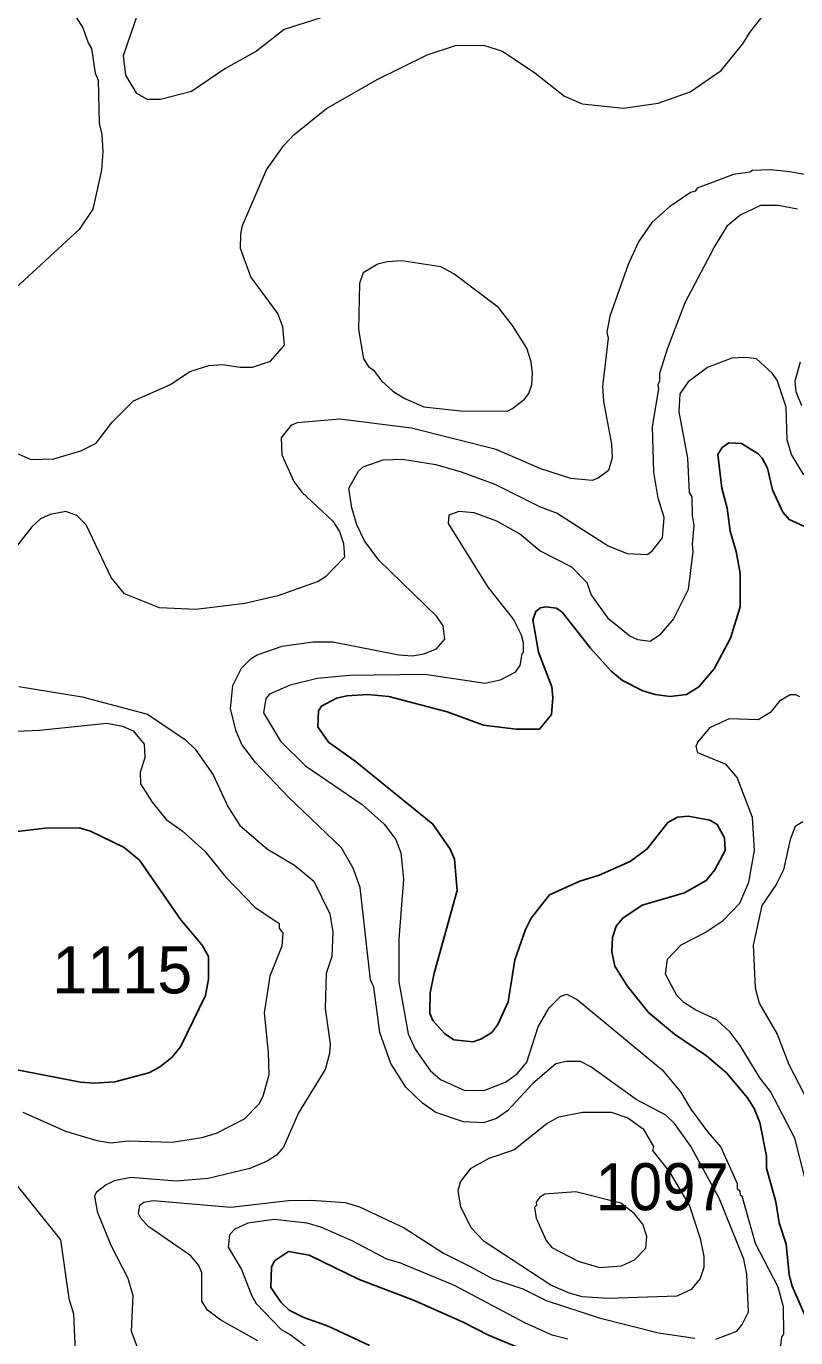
# Model space of a CAD drawing. Extents: x 447.8 to 473.9, y 7733.1 to 7760.8.
# Drawn here: x 470.525 to 471.833, y 7748.242 to 7750.473 of the extents above; entities that cross this region are included whole.
import ezdxf

# ---------------------------------------------------------------- set-up
doc = ezdxf.new("R2010")
doc.units = 0
doc.header["$LTSCALE"] = 0.032
doc.layers.add('1', color=7, linetype='Continuous', lineweight=25)
doc.layers.add('2', color=7, linetype='Continuous', lineweight=13)
doc.layers.add('21', color=7, linetype='Continuous')

msp = doc.modelspace()

# ---------------------------------------------------------------- linework, layer by layer
at = {"layer": '1'}
for points in [[(471.8474, 7749.6229), (471.8221, 7749.634), (471.8112, 7749.6468), (471.7936, 7749.6846), (471.7851, 7749.7213), (471.7765, 7749.7386), (471.7696, 7749.7458), (471.7411, 7749.7634), (471.7193, 7749.7647), (471.7085, 7749.7567), (471.7009, 7749.7449), (471.7075, 7749.6873), (471.7169, 7749.6532), (471.7221, 7749.6141), (471.7323, 7749.5799), (471.7386, 7749.5422), (471.7386, 7749.4858), (471.7225, 7749.4324), (471.6947, 7749.3801), (471.6687, 7749.3492), (471.6473, 7749.3366), (471.6197, 7749.3333), (471.5941, 7749.3366), (471.5731, 7749.3429), (471.539, 7749.3602), (471.5196, 7749.3761), (471.4842, 7749.4153), (471.4362, 7749.4762), (471.4263, 7749.483), (471.4085, 7749.4856), (471.3994, 7749.4838), (471.3911, 7749.4778), (471.3861, 7749.4635), (471.3961, 7749.4086), (471.4188, 7749.3494), (471.4204, 7749.3305), (471.4178, 7749.3027), (471.3973, 7749.2774), (471.3578, 7749.2774), (471.3023, 7749.2845), (471.2405, 7749.3068), (471.1411, 7749.3333), (471.1058, 7749.3365), (471.0702, 7749.3341), (471.0522, 7749.33), (471.0271, 7749.3167), (471.022, 7749.3085), (471.0205, 7749.2815), (471.0386, 7749.2552), (471.0842, 7749.2232), (471.2162, 7749.1159), (471.2457, 7749.0736), (471.2528, 7749.0564), (471.2577, 7749.0028), (471.2185, 7748.8624), (471.2116, 7748.8292), (471.2112, 7748.7947), (471.2163, 7748.7818), (471.2358, 7748.7597), (471.2517, 7748.749), (471.2849, 7748.7459), (471.2988, 7748.7506), (471.3163, 7748.7614), (471.3266, 7748.7754), (471.3442, 7748.8136), (471.3556, 7748.8849), (471.3737, 7748.9367), (471.3836, 7748.9563), (471.4147, 7748.9957), (471.4662, 7749.0191), (471.4991, 7749.0293), (471.5518, 7749.0524), (471.5809, 7749.0739), (471.6161, 7749.1185), (471.6325, 7749.1279), (471.6505, 7749.1297), (471.6873, 7749.1225)], [(471.6873, 7749.1225), (471.6999, 7749.1154), (471.7122, 7749.0926), (471.7131, 7749.0712), (471.6959, 7749.0382), (471.6813, 7749.0199)], [(470.4613, 7749.0978), (470.5568, 7749.1089), (470.6148, 7749.1097), (470.6341, 7749.1041), (470.6915, 7749.0762), (470.7172, 7749.0546), (470.7876, 7748.9534), (470.824, 7748.9101), (470.8344, 7748.8906), (470.8344, 7748.8521), (470.8293, 7748.8245), (470.7872, 7748.7371), (470.7724, 7748.7191), (470.7516, 7748.7024), (470.7332, 7748.6929), (470.6754, 7748.6776), (470.6399, 7748.6753), (470.6172, 7748.6769), (470.4645, 7748.7065)], [(471.6813, 7749.0199), (471.6439, 7748.999), (471.5723, 7748.9783), (471.5393, 7748.956), (471.5279, 7748.9422), (471.5215, 7748.9229), (471.5207, 7748.8986), (471.5255, 7748.8741), (471.5465, 7748.8412), (471.583, 7748.7957), (471.6271, 7748.7589), (471.6816, 7748.722), (471.7156, 7748.6927), (471.7513, 7748.6507), (471.7629, 7748.6325), (471.7724, 7748.6084), (471.7835, 7748.5514), (471.7837, 7748.531), (471.7996, 7748.4738), (471.8052, 7748.4376), (471.8173, 7748.4016), (471.822, 7748.3494), (471.8272, 7748.33), (471.8509, 7748.2756)], [(471.3955, 7748.2114), (471.3107, 7748.2465), (471.2676, 7748.2687), (471.1832, 7748.3062), (471.0908, 7748.3417), (471.0057, 7748.3828), (470.9708, 7748.389), (470.9468, 7748.373), (470.9419, 7748.3623), (470.9406, 7748.328), (470.9582, 7748.3023), (470.9721, 7748.2895), (470.9969, 7748.2766), (471.0384, 7748.2623), (471.1083, 7748.229)]]:
    msp.add_lwpolyline(points, dxfattribs=at)
at = {"layer": '2'}
for points in [[(471.1201, 7750.5174), (470.9632, 7750.4674), (470.9165, 7750.4309), (470.8623, 7750.4006), (470.8059, 7750.362), (470.7532, 7750.3486), (470.7308, 7750.3486), (470.7129, 7750.3587), (470.6943, 7750.3899), (470.6903, 7750.4231), (470.7158, 7750.4975)], [(470.7073, 7749.8361), (470.7702, 7749.8639), (470.8027, 7749.8858), (470.8354, 7749.896), (470.8582, 7749.8977), (470.8884, 7749.8929), (470.9094, 7749.8929), (470.9401, 7749.9034), (470.9642, 7749.9307), (470.9612, 7749.9615), (470.9523, 7749.9842), (470.9067, 7750.0469), (470.8891, 7750.095), (470.8894, 7750.1194), (470.8926, 7750.1344), (470.9335, 7750.2289), (470.9624, 7750.2694), (470.9806, 7750.2891), (471.0355, 7750.3331), (471.1215, 7750.3826), (471.2067, 7750.4244), (471.2545, 7750.4403), (471.3026, 7750.4411), (471.3349, 7750.4306), (471.3898, 7750.3938), (471.4401, 7750.3541), (471.47, 7750.3411), (471.5404, 7750.3337), (471.5996, 7750.3423), (471.6539, 7750.3615), (471.7064, 7750.3977), (471.7436, 7750.443), (471.7554, 7750.4622), (471.7966, 7750.515)], [(470.6092, 7750.4893), (470.6212, 7750.4701), (470.6298, 7750.445), (470.6359, 7750.4354), (470.6421, 7750.3934), (470.6469, 7750.3815), (470.6486, 7750.3075), (470.6533, 7750.2888), (470.6549, 7750.26), (470.6525, 7750.228), (470.6377, 7750.1617), (470.6146, 7750.1275), (470.4929, 7750.0149), (470.4775, 7749.9857), (470.4741, 7749.9632), (470.4744, 7749.9357), (470.4785, 7749.9283), (470.485, 7749.8896), (470.485, 7749.8441), (470.4803, 7749.8004), (470.4872, 7749.7636), (470.5052, 7749.7479), (470.5331, 7749.7359)], [(471.9195, 7750.208), (471.8233, 7750.2256), (471.7894, 7750.2288), (471.7599, 7750.2279), (471.7553, 7750.2248), (471.7277, 7750.2208), (471.666, 7750.1975), (471.6622, 7750.1926), (471.6546, 7750.1902), (471.6187, 7750.1657), (471.5885, 7750.1393), (471.5657, 7750.1064), (471.5481, 7750.0679), (471.5172, 7749.98)], [(471.1261, 7748.7617), (471.1159, 7748.8389), (471.1102, 7748.8509), (471.0926, 7749.0079), (471.0808, 7749.041), (471.0611, 7749.0755), (470.9707, 7749.1618), (470.9148, 7749.2209), (470.8911, 7749.2516), (470.8817, 7749.2743), (470.8722, 7749.3122), (470.8763, 7749.3517), (470.8909, 7749.3813), (470.9072, 7749.3975), (470.9173, 7749.4037), (470.9598, 7749.4185), (471.0121, 7749.4263), (471.0461, 7749.4263), (471.1583, 7749.4039), (471.1814, 7749.4024), (471.2007, 7749.4057), (471.2224, 7749.414), (471.2367, 7749.4305), (471.2337, 7749.4533), (471.2227, 7749.4693), (471.1241, 7749.5648), (471.1, 7749.5977), (471.0872, 7749.6252), (471.0782, 7749.6537), (471.0734, 7749.6873), (471.09, 7749.7163), (471.0976, 7749.7239), (471.1317, 7749.7358), (471.1644, 7749.7366), (471.2212, 7749.7277), (471.2646, 7749.7153), (471.3215, 7749.6943), (471.3988, 7749.6557), (471.4274, 7749.6446), (471.5143, 7749.5891), (471.5466, 7749.5763), (471.5812, 7749.5747), (471.59, 7749.5815), (471.6068, 7749.6029), (471.6096, 7749.6376), (471.5996, 7749.6702), (471.5918, 7749.7145), (471.5896, 7749.7923), (471.6007, 7749.8561), (471.5992, 7749.8638), (471.6024, 7749.87), (471.6025, 7749.8832), (471.615, 7749.9243), (471.6455, 7750.0032), (471.6947, 7750.0968), (471.7177, 7750.1347), (471.738, 7750.1517), (471.7738, 7750.1686), (471.8032, 7750.1686), (471.8364, 7750.1622)], [(471.5172, 7749.98), (471.5119, 7749.9525), (471.5141, 7749.9427), (471.5047, 7749.8602), (471.5063, 7749.8345), (471.5199, 7749.7624)], [(471.8472, 7749.7099), (471.8263, 7749.7444), (471.8189, 7749.7695), (471.8172, 7749.8252), (471.8016, 7749.871), (471.7931, 7749.8832), (471.7667, 7749.9073), (471.749, 7749.9097), (471.7245, 7749.9085), (471.6835, 7749.8924), (471.6506, 7749.8681), (471.6361, 7749.8477), (471.6345, 7749.8172), (471.649, 7749.7386), (471.6522, 7749.68), (471.6569, 7749.6728), (471.657, 7749.6409), (471.6602, 7749.6241), (471.657, 7749.5919), (471.6585, 7749.5799), (471.6505, 7749.5149), (471.6252, 7749.465), (471.6018, 7749.4371), (471.5856, 7749.4264), (471.5646, 7749.4294), (471.5512, 7749.4359), (471.5156, 7749.4643), (471.4857, 7749.5063), (471.4788, 7749.5264), (471.4528, 7749.5528), (471.3982, 7749.5806), (471.3638, 7749.6097), (471.3253, 7749.6314), (471.2863, 7749.6453), (471.2602, 7749.6475), (471.2433, 7749.6416), (471.2422, 7749.627), (471.3099, 7749.5188), (471.3535, 7749.4639), (471.3666, 7749.4379), (471.3699, 7749.4247), (471.3699, 7749.4075), (471.3675, 7749.4057), (471.364, 7749.3859), (471.3557, 7749.3736), (471.3305, 7749.3609), (471.3049, 7749.3551), (471.2023, 7749.3702), (471.0742, 7749.3686), (471.0195, 7749.3639), (470.9736, 7749.3525), (470.9385, 7749.3371), (470.9322, 7749.3299), (470.9282, 7749.3051), (470.9572, 7749.2572), (470.9999, 7749.2153), (471.0961, 7749.1495), (471.1336, 7749.1159), (471.1534, 7749.0898), (471.1616, 7749.0669), (471.1663, 7749.0223), (471.1584, 7748.9204), (471.1585, 7748.848), (471.1745, 7748.7591), (471.186, 7748.7332), (471.2115, 7748.6967), (471.2294, 7748.6819), (471.2707, 7748.6629), (471.3046, 7748.6633), (471.3398, 7748.677), (471.3601, 7748.6919), (471.3762, 7748.7111), (471.3951, 7748.7713), (471.4141, 7748.8033), (471.4338, 7748.8235), (471.4442, 7748.8265), (471.4616, 7748.8177), (471.6062, 7748.698), (471.6372, 7748.6606), (471.6547, 7748.631), (471.6836, 7748.592), (471.7062, 7748.5667), (471.7337, 7748.505)], [(471.841, 7749.9019), (471.8317, 7749.8692), (471.8333, 7749.8519), (471.8429, 7749.8282)], [(470.5331, 7749.7359), (470.5718, 7749.7374), (470.6173, 7749.7511), (470.6438, 7749.7637), (470.6706, 7749.7998), (470.7073, 7749.8361)], [(471.5199, 7749.7624), (471.5214, 7749.7389), (471.5148, 7749.7172), (471.4975, 7749.7042), (471.4869, 7749.7006), (471.4508, 7749.7039), (471.3998, 7749.72), (471.3241, 7749.7532), (471.1798, 7749.7893), (471.0579, 7749.8047), (470.9855, 7749.7984), (470.9748, 7749.7942), (470.958, 7749.7731), (470.9596, 7749.7439), (470.9797, 7749.6987), (470.9936, 7749.6807), (471.0463, 7749.6313), (471.0574, 7749.6138), (471.0645, 7749.5931), (471.066, 7749.5702), (471.0339, 7749.5367), (471.0212, 7749.5286), (470.9528, 7749.504), (470.8962, 7749.4914), (470.8134, 7749.481), (470.7511, 7749.4841), (470.6919, 7749.5075), (470.6692, 7749.5357), (470.6268, 7749.6251), (470.6109, 7749.641), (470.5922, 7749.6475), (470.5652, 7749.6428), (470.5489, 7749.6352), (470.5345, 7749.6217), (470.4979, 7749.575)], [(470.5122, 7749.3502), (470.62, 7749.3325), (470.7312, 7749.3032), (470.7954, 7749.2593), (470.8122, 7749.2433), (470.8427, 7749.2), (470.8673, 7749.1457), (470.8877, 7749.1135), (470.9349, 7749.0734), (470.981, 7749.046), (471.0139, 7749.0189), (471.0412, 7748.9633), (471.0462, 7748.9329), (471.0444, 7748.8906), (471.0348, 7748.8617), (471.0333, 7748.8024), (471.0413, 7748.7422), (471.0405, 7748.7259), (471.0332, 7748.6989), (470.9876, 7748.6248), (470.9625, 7748.5668), (470.9501, 7748.5528), (470.9344, 7748.5425), (470.9047, 7748.5301), (470.8342, 7748.5135), (470.7798, 7748.5087), (470.7027, 7748.5149), (470.6745, 7748.5094), (470.6604, 7748.5025), (470.6439, 7748.4893), (470.6407, 7748.4832), (470.6456, 7748.4573), (470.6687, 7748.4), (470.6977, 7748.3439), (470.7061, 7748.3141), (470.703, 7748.2536), (470.7147, 7748.2234)], [(471.8589, 7748.4745), (471.832, 7748.5819), (471.7903, 7748.661), (471.7722, 7748.6844), (471.739, 7748.7396), (471.722, 7748.7624), (471.6989, 7748.7833), (471.6636, 7748.7994), (471.6433, 7748.8126), (471.6311, 7748.8246), (471.6121, 7748.8608), (471.6155, 7748.8863), (471.6384, 7748.9109), (471.6796, 7748.9319), (471.7101, 7748.9522), (471.7381, 7748.9817), (471.7535, 7749.017), (471.7634, 7749.0713), (471.7598, 7749.127), (471.7338, 7749.1955), (471.7148, 7749.2175), (471.6667, 7749.2373), (471.6642, 7749.2486), (471.667, 7749.2556), (471.6883, 7749.2806), (471.7206, 7749.2957), (471.7696, 7749.2942), (471.7923, 7749.3078), (471.8074, 7749.3268), (471.824, 7749.3365), (471.8329, 7749.3365), (471.84, 7749.3329)], [(470.509, 7749.274), (470.5472, 7749.2756), (470.6617, 7749.2877), (470.6886, 7749.2828), (470.7067, 7749.2749), (470.7255, 7749.2517), (470.7262, 7749.2292), (470.7183, 7749.2035), (470.7189, 7749.1845), (470.7391, 7749.1533), (470.7629, 7749.1236), (470.7899, 7749.1047), (470.8286, 7749.0699), (470.8639, 7749.0258), (470.9132, 7748.9748), (470.9546, 7748.9468), (470.9549, 7748.9391), (470.961, 7748.9304), (470.9594, 7748.9083), (470.9388, 7748.8576), (470.9292, 7748.795), (470.9364, 7748.7278), (470.937, 7748.6898), (470.9268, 7748.6527), (470.9204, 7748.6395), (470.8954, 7748.6144), (470.8486, 7748.5902), (470.8236, 7748.5824), (470.7726, 7748.5743), (470.6979, 7748.5768), (470.6686, 7748.5735), (470.6456, 7748.5771), (470.5921, 7748.5929), (470.5196, 7748.6255)], [(471.8455, 7749.1198), (471.8322, 7749.1118), (471.8236, 7749.0897), (471.8123, 7749.0381), (471.7998, 7749.013), (471.7756, 7748.9774), (471.7612, 7748.9101), (471.7644, 7748.8377), (471.7711, 7748.8117), (471.8015, 7748.7588), (471.8218, 7748.7069), (471.8477, 7748.6568)], [(471.2686, 7748.6096), (471.2211, 7748.6254), (471.1987, 7748.6413), (471.1704, 7748.6687), (471.145, 7748.709), (471.1261, 7748.7617)], [(471.6974, 7748.2401), (471.7332, 7748.2538), (471.7422, 7748.2647), (471.753, 7748.2862), (471.7499, 7748.3506), (471.7451, 7748.376), (471.7031, 7748.4796), (471.6545, 7748.5686), (471.627, 7748.6066), (471.6123, 7748.6212), (471.5617, 7748.6476), (471.4848, 7748.7034), (471.4671, 7748.712), (471.4434, 7748.7121), (471.4256, 7748.7082), (471.3865, 7748.675), (471.3433, 7748.6286), (471.3245, 7748.6153), (471.3023, 7748.6079), (471.2686, 7748.6096)], [(470.4933, 7748.5207), (470.5827, 7748.409), (470.5972, 7748.3093), (470.6052, 7748.2833), (470.6077, 7748.2185)], [(471.7337, 7748.505), (471.7339, 7748.4961), (471.7384, 7748.4925), (471.7387, 7748.4857), (471.7418, 7748.4835), (471.7645, 7748.4033)], [(470.9185, 7748.2372), (470.8559, 7748.2725), (470.8332, 7748.2895), (470.8233, 7748.3044), (470.8232, 7748.3528), (470.8184, 7748.3651), (470.8048, 7748.3819), (470.733, 7748.4308), (470.7201, 7748.4448), (470.7159, 7748.4536), (470.7178, 7748.468), (470.7247, 7748.4732), (470.7408, 7748.4757), (470.8726, 7748.4645), (470.9707, 7748.4757), (471.0096, 7748.4765), (471.0669, 7748.4724), (471.0912, 7748.4653), (471.1673, 7748.4296), (471.2346, 7748.3863), (471.2818, 7748.3627), (471.3184, 7748.3425), (471.3693, 7748.3253), (471.4087, 7748.3056), (471.4989, 7748.276), (471.6001, 7748.2506), (471.662, 7748.2419)], [(471.4457, 7748.24), (471.4193, 7748.2466), (471.3724, 7748.2675), (471.2532, 7748.3313), (471.1602, 7748.3697), (471.1382, 7748.3761), (471.0789, 7748.4075), (471.0255, 7748.4307), (471.0025, 7748.4373), (470.9464, 7748.4436), (470.9015, 7748.4371), (470.8796, 7748.427), (470.8703, 7748.4176), (470.8682, 7748.3967), (470.8908, 7748.3583), (470.9077, 7748.3148), (470.9159, 7748.3009), (470.9584, 7748.2562), (470.9734, 7748.2481), (471.017, 7748.2153)], [(471.7645, 7748.4033), (471.8031, 7748.3292), (471.8117, 7748.2954), (471.8125, 7748.2485), (471.8093, 7748.2438), (471.8055, 7748.2147)]]:
    msp.add_lwpolyline(points, dxfattribs=at)
for points in [[(471.2519, 7750.0521), (471.23, 7750.064), (471.1637, 7750.074), (471.1388, 7750.0724), (471.1228, 7750.0683), (471.0975, 7750.0536), (471.0912, 7750.0355), (471.0895, 7749.9575), (471.0984, 7749.9071), (471.1067, 7749.8942), (471.1154, 7749.8883), (471.1289, 7749.8702), (471.1482, 7749.8526), (471.1684, 7749.8397), (471.2007, 7749.8259), (471.263, 7749.8191), (471.3424, 7749.8184), (471.3519, 7749.8226), (471.3721, 7749.8389), (471.3795, 7749.8484), (471.3843, 7749.8638), (471.3859, 7749.8829), (471.3835, 7749.9025), (471.376, 7749.9256), (471.3519, 7749.964), (471.3278, 7749.9944)], [(471.2639, 7748.4646), (471.2593, 7748.493), (471.2633, 7748.5074), (471.2815, 7748.5308), (471.312, 7748.5477), (471.3537, 7748.5622), (471.4103, 7748.6068), (471.4303, 7748.6181), (471.4706, 7748.6263), (471.5197, 7748.6262), (471.5479, 7748.6167), (471.5737, 7748.5979), (471.5916, 7748.5677), (471.5899, 7748.5611), (471.618, 7748.5253), (471.6525, 7748.4666), (471.671, 7748.411), (471.677, 7748.3805), (471.6769, 7748.3619), (471.6706, 7748.3429), (471.6556, 7748.3247), (471.6312, 7748.3133), (471.5145, 7748.309), (471.4704, 7748.3118), (471.4469, 7748.3185), (471.4167, 7748.3321), (471.3037, 7748.4063), (471.2819, 7748.429)], [(471.5785, 7748.395), (471.5799, 7748.4147), (471.5735, 7748.4355), (471.5586, 7748.4538), (471.5358, 7748.4715), (471.4594, 7748.4905), (471.4064, 7748.4868), (471.3976, 7748.4812), (471.392, 7748.4732), (471.3923, 7748.4672), (471.3892, 7748.4641), (471.3918, 7748.4459), (471.4089, 7748.4077), (471.4187, 7748.396), (471.4632, 7748.3729), (471.4995, 7748.362), (471.5371, 7748.3648), (471.5594, 7748.375)]]:
    msp.add_lwpolyline(points, close=True, dxfattribs=at)

# ---------------------------------------------------------------- texts
at = {"layer": '21'}
msp.add_text('1115', height=0.08, dxfattribs=at).set_placement((470.5691, 7748.8281))
at = {"layer": '21', "width": 0.95}
msp.add_text('1097', height=0.08, dxfattribs=at).set_placement((471.4931, 7748.4593))

doc.saveas('drawing.dxf')
